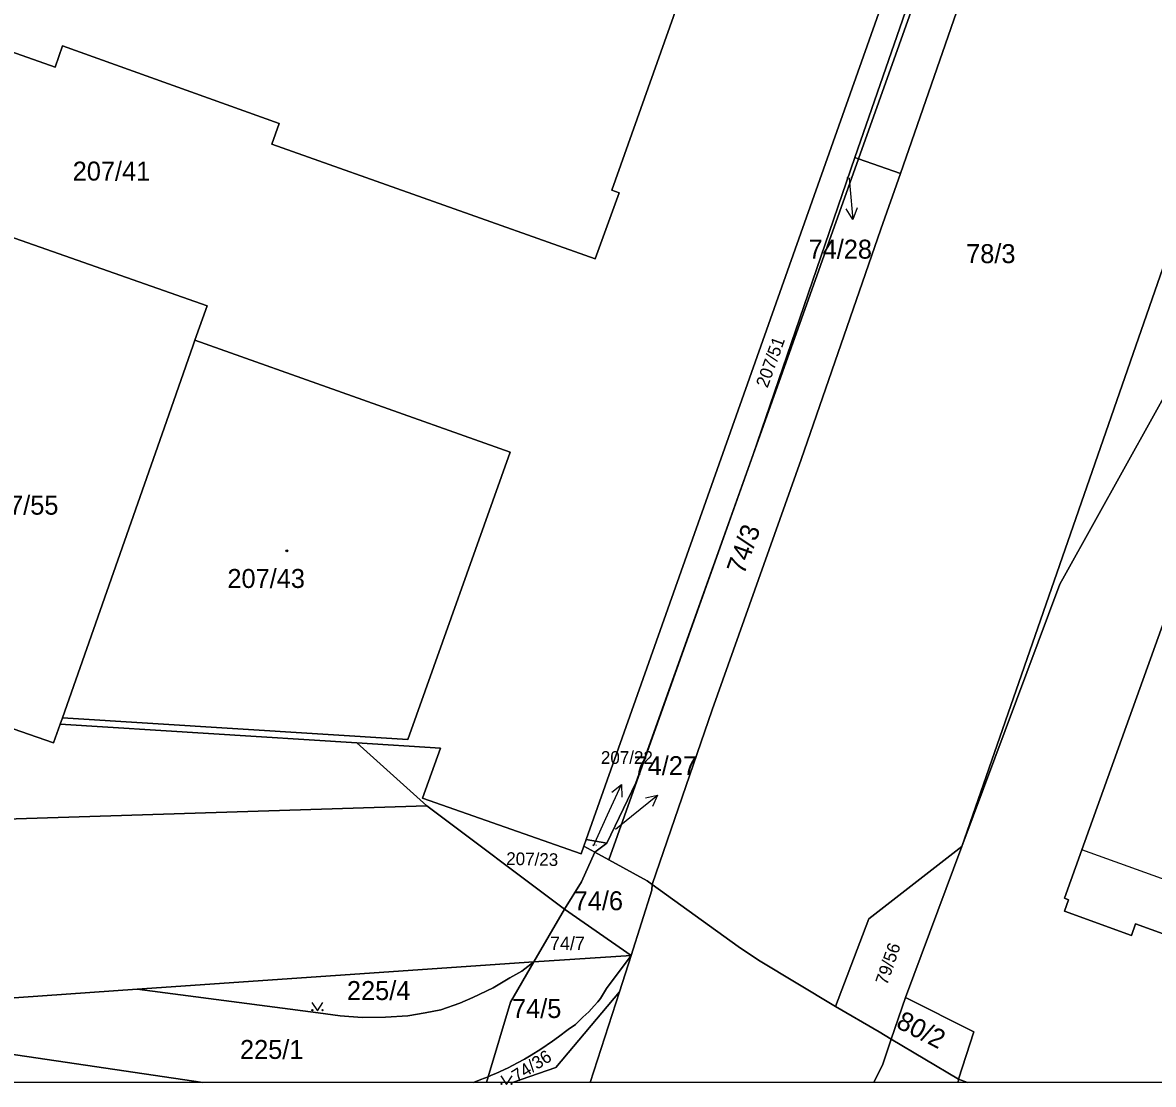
# Model space of a CAD drawing. Extents: x -598934 to -598196, y -1162208 to -1161502.
# Drawn here: x -598686.2 to -598584.8, y -1162207.1 to -1162112 of the extents above; entities that cross this region are included whole.
import ezdxf

# ---------------------------------------------------------------- set-up
doc = ezdxf.new("R2010")
doc.units = 0
for name, color, linetype in [('KN_CAR_KR', 7, 'Continuous'), ('KN_KULTURY', 7, 'Continuous'), ('KN_PARC_CIS_POM', 7, 'Continuous'), ('KN_PARC_CIS_POZ', 7, 'Continuous'), ('KN_PARC_CIS_STAV', 7, 'Continuous'), ('KN_PARC_PLOCHA', 7, 'Continuous'), ('PARC_C_SIPKA', 7, 'Continuous'), ('parcely_l', 7, 'Continuous')]:
    doc.layers.add(name, color=color, linetype=linetype)

msp = doc.modelspace()

# ---------------------------------------------------------------- linework, layer by layer
at = {"layer": 'KN_CAR_KR'}
msp.add_lwpolyline([(-598555.09, -1162199.12), (-598591.22, -1162186.11)], dxfattribs=at)
at = {"layer": 'KN_KULTURY'}
for points in [[(-598660.26, -1162199.79), (-598659.76, -1162200.54), (-598659.26, -1162199.79)], [(-598643.3, -1162206.39), (-598642.8, -1162207.14), (-598642.3, -1162206.39)]]:
    msp.add_lwpolyline(points, dxfattribs=at)
for centre, radius in [((-598662.5, -1162159.31), 0.09), ((-598662.5, -1162159.31), 0.0398), ((-598660.21, -1162200.49), 0.05), ((-598659.31, -1162200.49), 0.05), ((-598643.25, -1162207.09), 0.05), ((-598642.35, -1162207.09), 0.05)]:
    msp.add_circle(centre, radius, dxfattribs=at)
at = {"layer": 'KN_PARC_PLOCHA'}
for points in [[(-598668.55, -1162035.34), (-598674.02, -1162044.9), (-598673, -1162045.47), (-598673.6, -1162046.51), (-598674.03, -1162046.15), (-598710.29, -1162094.83), (-598710.79, -1162094.46), (-598717.77, -1162103.75), (-598683.27, -1162115.94), (-598682.6, -1162114.05), (-598663.19, -1162120.99), (-598663.85, -1162122.86), (-598634.84, -1162133.15), (-598632.69, -1162127.23), (-598633.35, -1162126.99), (-598616.44, -1162079.32), (-598616.93, -1162078.93), (-598616.33, -1162077.89), (-598615.31, -1162078.48), (-598609.79, -1162068.96), (-598613.68, -1162066.69), (-598612.54, -1162064.68), (-598663.42, -1162035.55), (-598664.65, -1162037.57)], [(-598668.55, -1162035.34), (-598664.65, -1162037.57), (-598663.42, -1162035.55), (-598612.54, -1162064.68), (-598613.68, -1162066.69), (-598609.79, -1162068.96), (-598615.31, -1162078.48), (-598616.33, -1162077.89), (-598616.93, -1162078.93), (-598616.44, -1162079.32), (-598633.35, -1162126.99), (-598632.69, -1162127.23), (-598634.84, -1162133.15), (-598663.85, -1162122.86), (-598663.19, -1162120.99), (-598682.6, -1162114.05), (-598683.27, -1162115.94), (-598717.77, -1162103.75), (-598710.79, -1162094.46), (-598710.29, -1162094.83), (-598674.03, -1162046.15), (-598673.6, -1162046.51), (-598673, -1162045.47), (-598674.02, -1162044.9)], [(-598589.75, -1162074.37), (-598600.18, -1162104.44), (-598607.47, -1162125.48), (-598611.23, -1162124.16), (-598596.81, -1162083.67), (-598597.43, -1162083.42), (-598602.15, -1162081.52), (-598602.32, -1162081.45), (-598598.54, -1162071.79), (-598594.12, -1162073.38), (-598593.91, -1162072.84), (-598590.45, -1162074.11)], [(-598597.43, -1162083.42), (-598597.71, -1162084.28), (-598607.02, -1162110.95), (-598611.57, -1162124.04), (-598620.68, -1162150.69), (-598631.21, -1162180.12), (-598633.8, -1162185.51), (-598635.66, -1162185.2), (-598604.68, -1162097.65), (-598600.34, -1162086.32), (-598602.15, -1162081.52)], [(-598611.23, -1162124.16), (-598611.57, -1162124.04), (-598607.02, -1162110.95), (-598597.71, -1162084.28), (-598597.43, -1162083.42), (-598596.81, -1162083.67)], [(-598574.38, -1162113.1), (-598573.66, -1162113.42), (-598571.78, -1162114.17), (-598570.61, -1162114.73), (-598582.14, -1162142.42), (-598592.78, -1162161.54), (-598593.18, -1162162.3), (-598601.97, -1162185.82), (-598576.38, -1162112.22)], [(-598607.47, -1162125.48), (-598609.23, -1162130.49), (-598616.39, -1162151.12), (-598624.36, -1162173.57), (-598629.75, -1162189.23), (-598630.19, -1162188.9), (-598633.62, -1162187.01), (-598620.68, -1162150.69), (-598611.23, -1162124.16)], [(-598611.23, -1162124.16), (-598620.68, -1162150.69), (-598611.57, -1162124.04)], [(-598682.62, -1162174.28), (-598673.09, -1162147.12), (-598670.89, -1162140.86), (-598670.74, -1162140.44), (-598642.46, -1162150.48), (-598651.66, -1162176.21)], [(-598572.4, -1162143.94), (-598540.53, -1162158.84), (-598545.64, -1162172.87), (-598555.09, -1162199.12), (-598556.67, -1162203.5), (-598586.39, -1162192.76), (-598586.77, -1162193.8), (-598592.78, -1162191.62), (-598592.4, -1162190.59), (-598592.78, -1162190.45), (-598591.22, -1162186.11), (-598581.77, -1162159.86), (-598579.08, -1162160.83), (-598578.86, -1162160.22), (-598579.61, -1162159.95), (-598577.88, -1162155.15), (-598577.12, -1162155.42), (-598572.91, -1162143.76)], [(-598633.62, -1162187.01), (-598634.89, -1162186.31), (-598633.8, -1162185.51), (-598631.21, -1162180.12), (-598620.68, -1162150.69)], [(-598635.87, -1162185.78), (-598634.89, -1162186.31), (-598636.08, -1162188.99), (-598637.59, -1162191.43), (-598649.94, -1162182.16), (-598656.22, -1162176.53), (-598648.72, -1162177), (-598650.32, -1162181.47), (-598636.11, -1162186.46)], [(-598637.59, -1162191.43), (-598640.36, -1162196.15), (-598675.91, -1162198.62), (-598710.32, -1162201.02), (-598751.03, -1162195.05), (-598751.65, -1162185.4), (-598734.98, -1162184.85), (-598649.94, -1162182.16)], [(-598633.8, -1162185.51), (-598634.89, -1162186.31), (-598635.87, -1162185.78), (-598635.66, -1162185.2)], [(-598633.62, -1162187.01), (-598630.19, -1162188.9), (-598629.75, -1162189.23), (-598629.76, -1162189.72), (-598631.62, -1162195.59), (-598637.59, -1162191.43), (-598636.08, -1162188.99), (-598634.89, -1162186.31)], [(-598607.03, -1162199.36), (-598608.3, -1162203.08), (-598609.39, -1162202.44), (-598613.3, -1162200.15), (-598610.3, -1162192.29), (-598601.97, -1162185.82)], [(-598613.3, -1162200.15), (-598609.39, -1162202.44), (-598608.3, -1162203.08), (-598609.07, -1162205.32), (-598609.87, -1162206.96), (-598635.31, -1162206.96), (-598632.66, -1162198.86), (-598631.62, -1162195.59), (-598629.76, -1162189.72), (-598629.75, -1162189.23), (-598622.04, -1162194.78), (-598620.21, -1162196.02)], [(-598631.62, -1162195.59), (-598640.36, -1162196.15), (-598637.59, -1162191.43)], [(-598710.32, -1162201.02), (-598670.03, -1162206.96), (-598733.71, -1162206.96), (-598739.53, -1162206.22), (-598739.63, -1162206.96), (-598778.08, -1162206.96), (-598778.24, -1162205.41), (-598778.88, -1162200.74), (-598778.65, -1162199.46), (-598778.25, -1162198.37), (-598776.78, -1162196.32), (-598774.57, -1162194.79), (-598772.64, -1162193.77), (-598769.79, -1162192.92), (-598765.65, -1162192.75), (-598751.03, -1162195.05)], [(-598644.44, -1162206.46), (-598645.09, -1162206.69), (-598645.75, -1162206.96), (-598670.03, -1162206.96), (-598710.32, -1162201.02), (-598675.91, -1162198.62), (-598659.7, -1162200.73), (-598657.73, -1162201.01), (-598655.73, -1162201.15), (-598653.65, -1162201.11), (-598651.64, -1162200.99), (-598650.11, -1162200.72), (-598648.68, -1162200.45), (-598646.99, -1162199.85), (-598645.81, -1162199.36), (-598644.01, -1162198.5), (-598642.51, -1162197.6), (-598641.44, -1162196.99), (-598640.36, -1162196.15), (-598642.44, -1162199.78)], [(-598675.91, -1162198.62), (-598640.36, -1162196.15), (-598641.44, -1162196.99), (-598642.51, -1162197.6), (-598644.01, -1162198.5), (-598645.81, -1162199.36), (-598646.99, -1162199.85), (-598648.68, -1162200.45), (-598650.11, -1162200.72), (-598651.64, -1162200.99), (-598653.65, -1162201.11), (-598655.73, -1162201.15), (-598657.73, -1162201.01), (-598659.7, -1162200.73)], [(-598632.66, -1162198.86), (-598638.38, -1162205.64), (-598642.25, -1162206.96), (-598644.59, -1162206.96), (-598644.44, -1162206.46), (-598644.15, -1162206.31), (-598643.77, -1162206.17), (-598642.65, -1162205.65), (-598641.81, -1162205.21), (-598641.18, -1162204.88), (-598640.58, -1162204.52), (-598639.73, -1162203.98), (-598638.69, -1162203.27), (-598638.14, -1162202.89), (-598637.26, -1162202.21), (-598636.63, -1162201.76), (-598635.95, -1162201.12), (-598635.42, -1162200.65), (-598634.93, -1162200.11), (-598634.61, -1162199.75), (-598634.38, -1162199.44), (-598633.83, -1162198.56), (-598631.62, -1162195.59)], [(-598644.44, -1162206.46), (-598642.44, -1162199.78), (-598640.36, -1162196.15), (-598631.62, -1162195.59), (-598633.83, -1162198.56), (-598634.38, -1162199.44), (-598634.61, -1162199.75), (-598634.93, -1162200.11), (-598635.42, -1162200.65), (-598635.95, -1162201.12), (-598636.63, -1162201.76), (-598637.26, -1162202.21), (-598638.14, -1162202.89), (-598638.69, -1162203.27), (-598639.73, -1162203.98), (-598640.58, -1162204.52), (-598641.18, -1162204.88), (-598641.81, -1162205.21), (-598642.65, -1162205.65), (-598643.77, -1162206.17), (-598644.15, -1162206.31)], [(-598635.31, -1162206.96), (-598642.25, -1162206.96), (-598638.38, -1162205.64), (-598632.66, -1162198.86)], [(-598602.26, -1162206.67), (-598608.3, -1162203.08), (-598607.03, -1162199.36), (-598600.89, -1162202.44)], [(-598602.26, -1162206.67), (-598602.31, -1162206.96), (-598609.87, -1162206.96), (-598609.07, -1162205.32), (-598608.3, -1162203.08)], [(-598644.59, -1162206.96), (-598645.75, -1162206.96), (-598645.09, -1162206.69), (-598644.44, -1162206.46)], [(-598601.46, -1162206.96), (-598602.31, -1162206.96), (-598602.26, -1162206.67)]]:
    msp.add_lwpolyline(points, close=True, dxfattribs=at)
for points in [[(-598564.74, -1162050.65), (-598555.77, -1162053.54), (-598559.33, -1162063.57), (-598566.94, -1162060.47), (-598582.73, -1162097.08), (-598586.56, -1162103.9), (-598588.64, -1162106.82), (-598577.56, -1162111.7), (-598576.38, -1162112.22), (-598601.97, -1162185.82), (-598610.3, -1162192.29), (-598613.3, -1162200.15), (-598620.21, -1162196.02), (-598622.04, -1162194.78), (-598629.75, -1162189.23), (-598624.36, -1162173.57), (-598616.39, -1162151.12), (-598609.23, -1162130.49), (-598607.47, -1162125.48), (-598600.18, -1162104.44), (-598589.75, -1162074.37), (-598588.43, -1162070.55), (-598582.71, -1162054.06), (-598579.44, -1162044.4)], [(-598604.68, -1162097.65), (-598635.66, -1162185.2), (-598635.87, -1162185.78), (-598636.11, -1162186.46), (-598650.32, -1162181.47), (-598648.72, -1162177), (-598656.22, -1162176.53), (-598682.83, -1162174.86), (-598682.62, -1162174.28), (-598651.66, -1162176.21), (-598642.46, -1162150.48), (-598670.74, -1162140.44), (-598669.65, -1162137.35), (-598720.2, -1162119.59)], [(-598720.2, -1162119.59), (-598669.65, -1162137.35), (-598670.74, -1162140.44), (-598670.89, -1162140.86), (-598673.09, -1162147.12), (-598682.62, -1162174.28), (-598682.83, -1162174.86), (-598683.41, -1162176.51), (-598688.54, -1162174.77)], [(-598537.06, -1162206.96), (-598601.46, -1162206.96), (-598602.26, -1162206.67), (-598600.89, -1162202.44), (-598607.03, -1162199.36), (-598601.97, -1162185.82), (-598593.18, -1162162.3), (-598592.78, -1162161.54), (-598582.14, -1162142.42)], [(-598581.77, -1162159.86), (-598591.22, -1162186.11), (-598592.78, -1162190.45), (-598592.4, -1162190.59), (-598592.78, -1162191.62), (-598586.77, -1162193.8), (-598586.39, -1162192.76), (-598556.67, -1162203.5)], [(-598688.54, -1162174.77), (-598683.41, -1162176.51), (-598682.83, -1162174.86), (-598656.22, -1162176.53), (-598649.94, -1162182.16), (-598734.98, -1162184.85)]]:
    msp.add_lwpolyline(points, dxfattribs=at)
at = {"layer": 'PARC_C_SIPKA'}
for points in [[(-598612.09, -1162125.91), (-598612.03, -1162126.62), (-598611.76, -1162129.61)], [(-598611.35, -1162128.57), (-598611.76, -1162129.61), (-598612.35, -1162128.66)], [(-598635.01, -1162185.76), (-598633.74, -1162182.99), (-598632.49, -1162180.26)], [(-598633.36, -1162180.96), (-598632.49, -1162180.26), (-598632.45, -1162181.38)], [(-598633.02, -1162184.25), (-598631.59, -1162183.09), (-598629.25, -1162181.22)], [(-598630.34, -1162181.45), (-598629.25, -1162181.22), (-598629.71, -1162182.23)]]:
    msp.add_lwpolyline(points, dxfattribs=at)
at = {"layer": 'parcely_l'}
for points in [[(-598668.55, -1162035.34), (-598664.65, -1162037.57), (-598663.42, -1162035.55), (-598612.54, -1162064.68), (-598613.68, -1162066.69), (-598609.79, -1162068.96), (-598615.31, -1162078.48), (-598616.33, -1162077.89), (-598616.93, -1162078.93), (-598616.44, -1162079.32), (-598633.35, -1162126.99), (-598632.69, -1162127.23), (-598634.84, -1162133.15), (-598663.85, -1162122.86), (-598663.19, -1162120.99), (-598682.6, -1162114.05), (-598683.27, -1162115.94), (-598717.77, -1162103.75)], [(-598607.47, -1162125.48), (-598600.18, -1162104.44), (-598589.75, -1162074.37)], [(-598611.57, -1162124.04), (-598607.02, -1162110.95), (-598597.71, -1162084.28), (-598597.43, -1162083.42)], [(-598597.43, -1162083.42), (-598596.81, -1162083.67), (-598611.23, -1162124.16)], [(-598604.68, -1162097.65), (-598635.66, -1162185.2)], [(-598576.38, -1162112.22), (-598601.97, -1162185.82)], [(-598601.97, -1162185.82), (-598593.18, -1162162.3), (-598592.78, -1162161.54), (-598582.14, -1162142.42), (-598570.61, -1162114.73)], [(-598727.76, -1162120.71), (-598725.34, -1162117.61), (-598720.2, -1162119.59), (-598669.65, -1162137.35), (-598670.74, -1162140.44)], [(-598620.68, -1162150.69), (-598611.57, -1162124.04)], [(-598611.23, -1162124.16), (-598620.68, -1162150.69)], [(-598611.57, -1162124.04), (-598611.23, -1162124.16)], [(-598607.47, -1162125.48), (-598611.23, -1162124.16)], [(-598629.75, -1162189.23), (-598624.36, -1162173.57), (-598616.39, -1162151.12), (-598609.23, -1162130.49), (-598607.47, -1162125.48)], [(-598682.62, -1162174.28), (-598673.09, -1162147.12), (-598670.89, -1162140.86), (-598670.74, -1162140.44)], [(-598670.74, -1162140.44), (-598642.46, -1162150.48), (-598651.66, -1162176.21), (-598682.62, -1162174.28)], [(-598572.4, -1162143.94), (-598572.91, -1162143.76), (-598577.12, -1162155.42), (-598577.88, -1162155.15), (-598579.61, -1162159.95), (-598578.86, -1162160.22), (-598579.08, -1162160.83), (-598581.77, -1162159.86), (-598591.22, -1162186.11), (-598592.78, -1162190.45), (-598592.4, -1162190.59), (-598592.78, -1162191.62), (-598586.77, -1162193.8), (-598586.39, -1162192.76), (-598556.67, -1162203.5), (-598555.09, -1162199.12), (-598545.64, -1162172.87), (-598540.53, -1162158.84)], [(-598633.8, -1162185.51), (-598631.21, -1162180.12), (-598620.68, -1162150.69)], [(-598620.68, -1162150.69), (-598633.62, -1162187.01)], [(-598682.83, -1162174.86), (-598683.41, -1162176.51), (-598688.54, -1162174.77)], [(-598682.62, -1162174.28), (-598682.83, -1162174.86)], [(-598656.22, -1162176.53), (-598682.83, -1162174.86)], [(-598635.87, -1162185.78), (-598636.11, -1162186.46), (-598650.32, -1162181.47), (-598648.72, -1162177), (-598656.22, -1162176.53)], [(-598649.94, -1162182.16), (-598656.22, -1162176.53)], [(-598751.65, -1162185.4), (-598734.98, -1162184.85), (-598649.94, -1162182.16)], [(-598649.94, -1162182.16), (-598637.59, -1162191.43)], [(-598635.87, -1162185.78), (-598635.66, -1162185.2)], [(-598635.66, -1162185.2), (-598633.8, -1162185.51)], [(-598634.89, -1162186.31), (-598636.08, -1162188.99), (-598637.59, -1162191.43)], [(-598634.89, -1162186.31), (-598635.87, -1162185.78)], [(-598633.8, -1162185.51), (-598634.89, -1162186.31)], [(-598633.62, -1162187.01), (-598634.89, -1162186.31)], [(-598601.97, -1162185.82), (-598610.3, -1162192.29), (-598613.3, -1162200.15)], [(-598607.03, -1162199.36), (-598601.97, -1162185.82)], [(-598629.75, -1162189.23), (-598630.19, -1162188.9), (-598633.62, -1162187.01)], [(-598631.62, -1162195.59), (-598629.76, -1162189.72), (-598629.75, -1162189.23)], [(-598629.75, -1162189.23), (-598622.04, -1162194.78), (-598620.21, -1162196.02), (-598613.3, -1162200.15)], [(-598637.59, -1162191.43), (-598640.36, -1162196.15)], [(-598637.59, -1162191.43), (-598631.62, -1162195.59)], [(-598675.91, -1162198.62), (-598659.7, -1162200.73), (-598657.73, -1162201.01), (-598655.73, -1162201.15), (-598653.65, -1162201.11), (-598651.64, -1162200.99), (-598650.11, -1162200.72), (-598648.68, -1162200.45), (-598646.99, -1162199.85), (-598645.81, -1162199.36), (-598644.01, -1162198.5), (-598642.51, -1162197.6), (-598641.44, -1162196.99), (-598640.36, -1162196.15)], [(-598675.91, -1162198.62), (-598640.36, -1162196.15)], [(-598631.62, -1162195.59), (-598633.83, -1162198.56), (-598634.38, -1162199.44), (-598634.61, -1162199.75), (-598634.93, -1162200.11), (-598635.42, -1162200.65), (-598635.95, -1162201.12), (-598636.63, -1162201.76), (-598637.26, -1162202.21), (-598638.14, -1162202.89), (-598638.69, -1162203.27), (-598639.73, -1162203.98), (-598640.58, -1162204.52), (-598641.18, -1162204.88), (-598641.81, -1162205.21), (-598642.65, -1162205.65), (-598643.77, -1162206.17), (-598644.15, -1162206.31), (-598644.44, -1162206.46)], [(-598644.44, -1162206.46), (-598642.44, -1162199.78), (-598640.36, -1162196.15)], [(-598640.36, -1162196.15), (-598631.62, -1162195.59)], [(-598632.66, -1162198.86), (-598631.62, -1162195.59)], [(-598710.32, -1162201.02), (-598675.91, -1162198.62)], [(-598642.25, -1162206.96), (-598638.38, -1162205.64), (-598632.66, -1162198.86)], [(-598635.31, -1162206.96), (-598632.66, -1162198.86)], [(-598607.03, -1162199.36), (-598608.3, -1162203.08)], [(-598602.26, -1162206.67), (-598600.89, -1162202.44), (-598607.03, -1162199.36)], [(-598613.3, -1162200.15), (-598609.39, -1162202.44), (-598608.3, -1162203.08)], [(-598670.03, -1162206.96), (-598710.32, -1162201.02)], [(-598608.3, -1162203.08), (-598609.07, -1162205.32), (-598609.87, -1162206.96)], [(-598602.26, -1162206.67), (-598608.3, -1162203.08)], [(-598644.44, -1162206.46), (-598645.09, -1162206.69), (-598645.75, -1162206.96)], [(-598644.59, -1162206.96), (-598644.44, -1162206.46)], [(-598602.31, -1162206.96), (-598602.26, -1162206.67)], [(-598601.46, -1162206.96), (-598602.26, -1162206.67)], [(-598670.03, -1162206.96), (-598733.71, -1162206.96)], [(-598645.75, -1162206.96), (-598670.03, -1162206.96)], [(-598644.59, -1162206.96), (-598645.75, -1162206.96)], [(-598642.25, -1162206.96), (-598644.59, -1162206.96)], [(-598635.31, -1162206.96), (-598642.25, -1162206.96)], [(-598609.87, -1162206.96), (-598635.31, -1162206.96)], [(-598602.31, -1162206.96), (-598609.87, -1162206.96)], [(-598601.46, -1162206.96), (-598602.31, -1162206.96)], [(-598537.06, -1162206.96), (-598601.46, -1162206.96)]]:
    msp.add_lwpolyline(points, dxfattribs=at)

# ---------------------------------------------------------------- texts
at = {"layer": 'KN_PARC_CIS_POM'}
for s, p in [('74/28', (-598612.32, -1162125.91)), ('74/27', (-598633.13, -1162184.25)), ('207/22', (-598635.14, -1162185.76))]:
    msp.add_text(s, height=0.1, dxfattribs=at).set_placement(p)
at = {"layer": 'KN_PARC_CIS_POZ'}
for s, height, p in [('207/41', 1.7, (-598681.7, -1162126.12)), ('74/28', 1.7, (-598615.72, -1162133.12)), ('78/3', 1.7, (-598601.59, -1162133.52)), ('207/55', 1.7, (-598689.93, -1162156.07)), ('207/22', 1.14, (-598634.34, -1162178.41)), ('74/27', 1.7, (-598631.41, -1162179.42)), ('74/6', 1.7, (-598636.78, -1162191.53)), ('74/7', 1.2, (-598638.9, -1162195.1)), ('225/4', 1.7, (-598657.11, -1162199.58)), ('74/5', 1.7, (-598642.31, -1162201.19)), ('225/1', 1.7, (-598666.7, -1162204.86))]:
    msp.add_text(s, height=height, dxfattribs=at).set_placement(p)
for s, height, rotation, p in [('207/51', 1.14, 70.1016, (-598619.4, -1162144.77)), ('74/3', 1.7, 70.1986, (-598621.51, -1162161.51)), ('207/23', 1.14, 358.6094, (-598642.84, -1162187.46)), ('79/56', 1.14, 71.0997, (-598608.68, -1162198.31)), ('80/2', 1.7, 332.9993, (-598607.97, -1162202)), ('74/36', 1.14, 32.4599, (-598641.86, -1162206.99))]:
    msp.add_text(s, height=height, rotation=rotation, dxfattribs=at).set_placement(p)
at = {"layer": 'KN_PARC_CIS_STAV'}
msp.add_text('207/43', height=1.7, dxfattribs=at).set_placement((-598667.83, -1162162.64))

doc.saveas('drawing.dxf')
